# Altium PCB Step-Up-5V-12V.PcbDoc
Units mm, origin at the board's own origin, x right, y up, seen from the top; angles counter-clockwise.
Board outline 43.5 x 30 mm, 2 copper layers (Top Layer, Bottom Layer), stack 1.601 mm thick; 18 components, 9 nets, 46 pads, 0 vias.
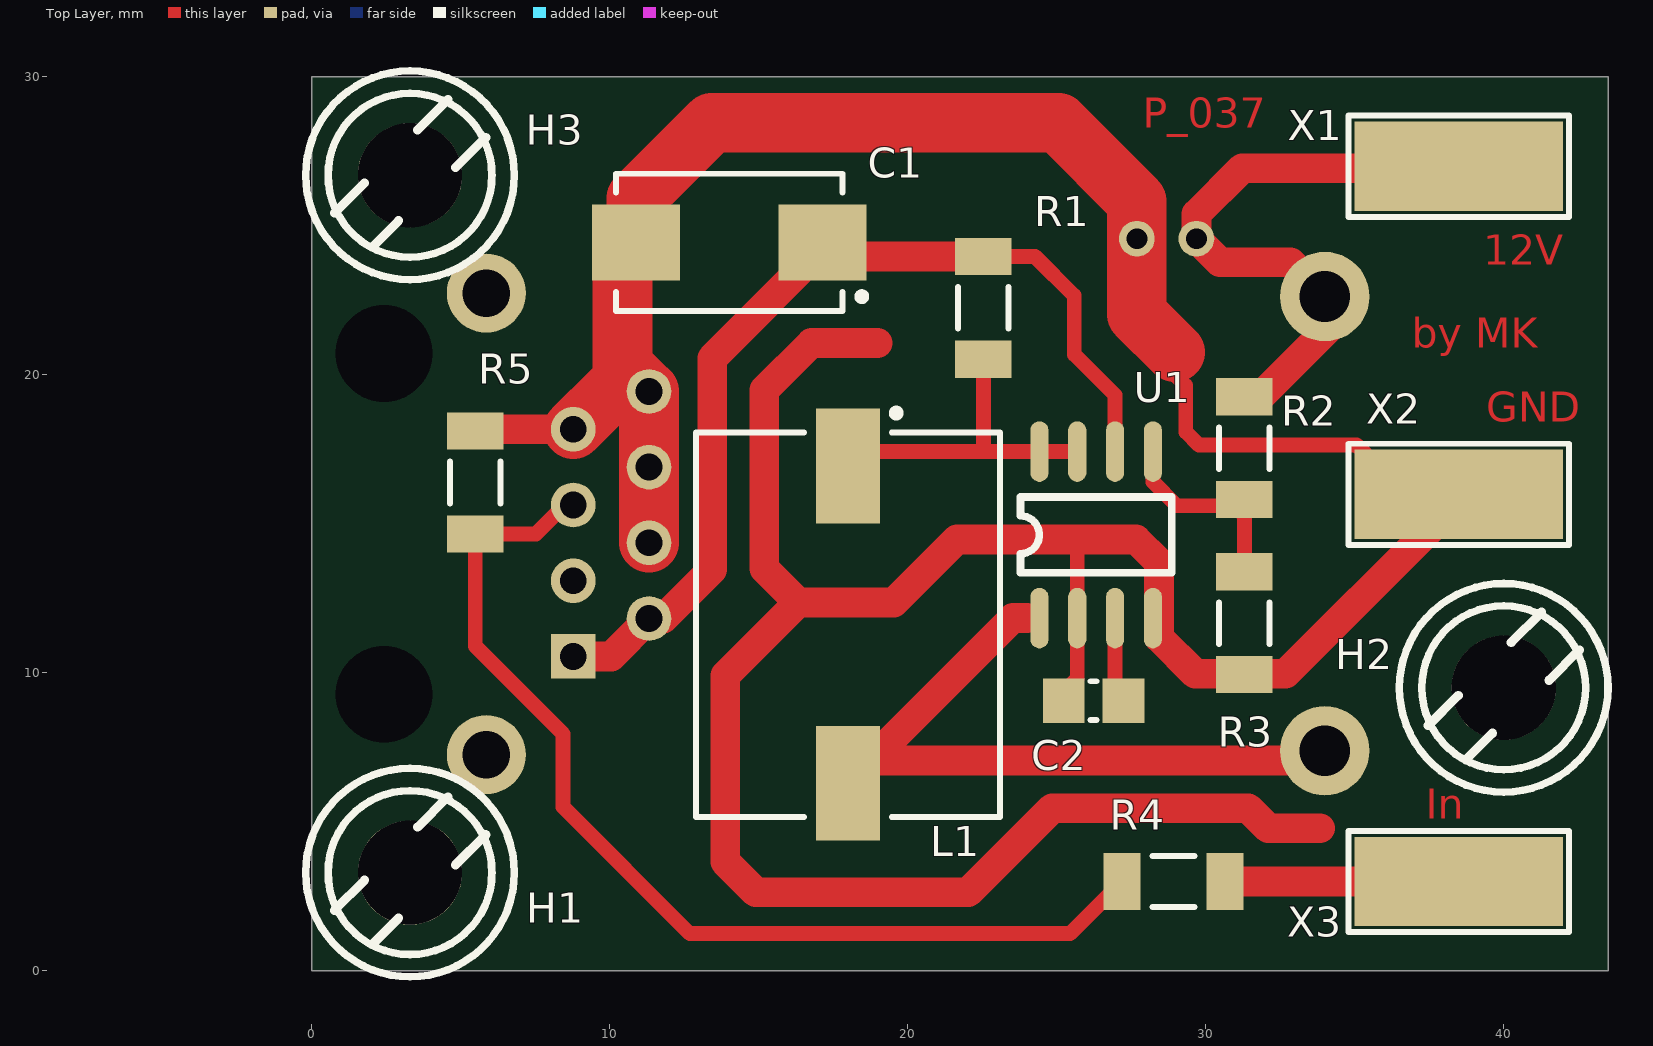
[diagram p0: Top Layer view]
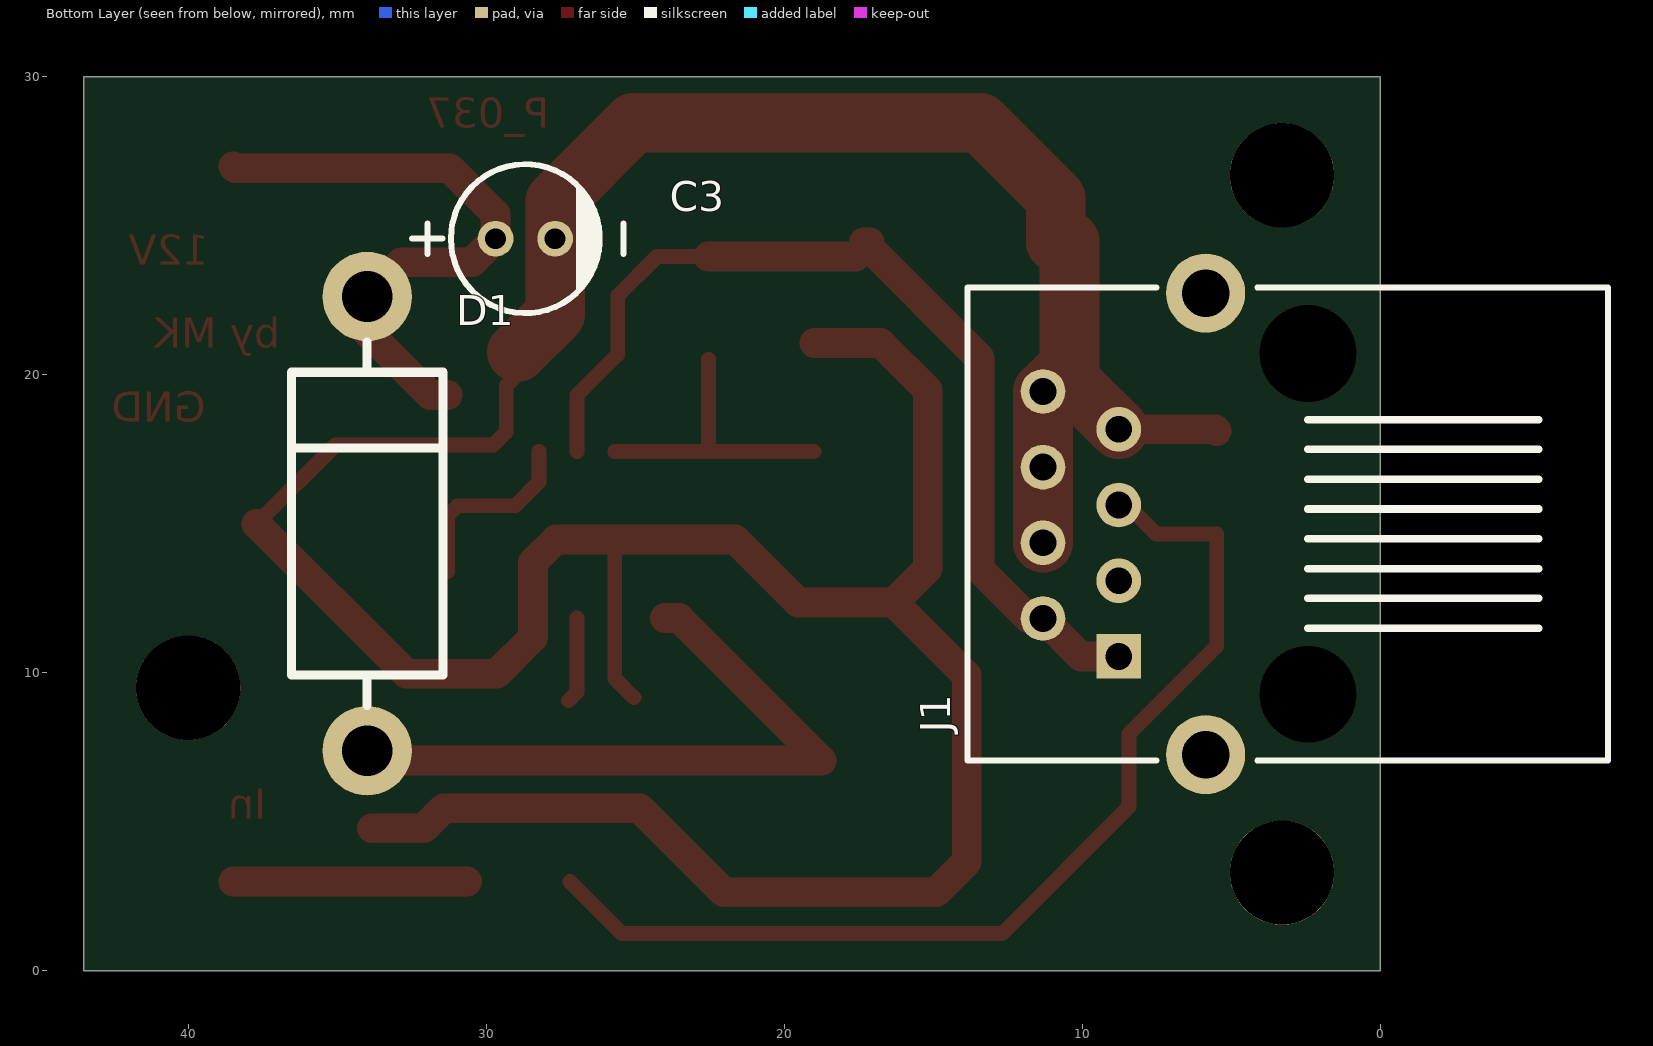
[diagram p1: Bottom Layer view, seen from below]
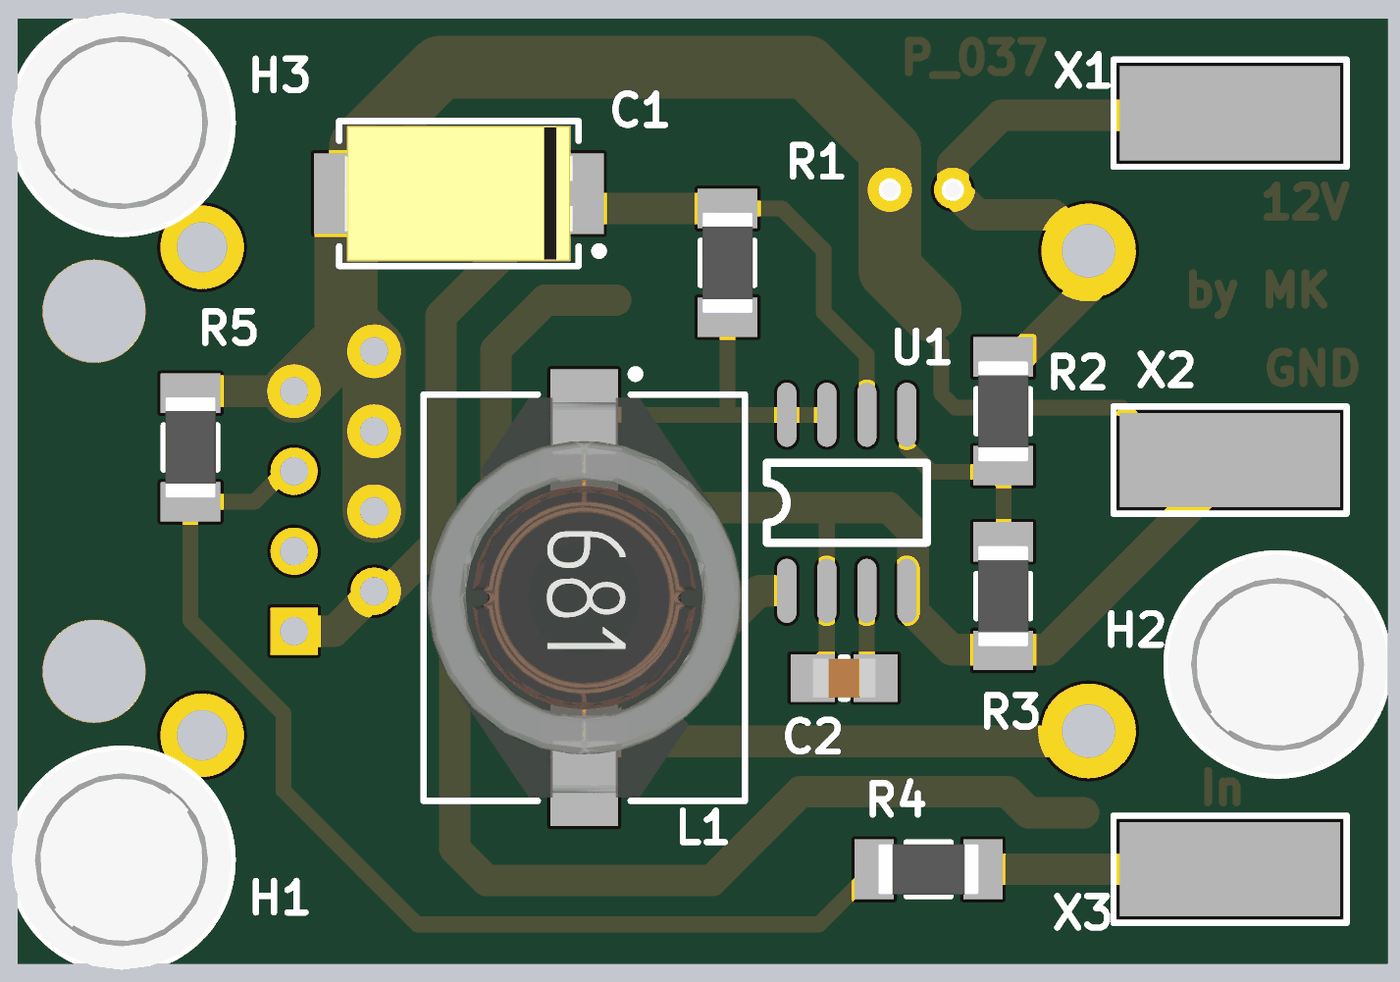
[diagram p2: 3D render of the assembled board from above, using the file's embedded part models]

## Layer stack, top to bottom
Top Layer: signal copper 0.0356
Dielectric: core 1.53, FR-4, Dk 4.8
Bottom Layer: signal copper 0.0356

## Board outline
0,0 0,30 43.5,30 43.5,0

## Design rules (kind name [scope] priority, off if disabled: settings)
Clearance [All] p1: gap=0.2
ComponentClearance [All] p1 off: gap=0.254 collisioncheckmode=3 verticalgap=0.254 showdistances=FALSE
FabricationTestPointUsage TestPointUsage [All] p1: valid=0 allowmultiple=FALSE
FabricationTestpoint Testpoint [All] p1: side=3 testpointundercomponent=TRUE minsize=1.016 maxsize=2.54 preferedsize=1.524 minholesize=0 maxholesize=1.016 preferedholesize=0.813 testpointgrid=0.025 allowsidetop=TRUE allowsidebottom=TRUE usegrid=TRUE gridtolerance=0
HoleSize [All] p1: absolutevalues=TRUE maxlimit=4 minlimit=0.025 maxpercent=80.000 minpercent=20.000
PlaneConnect [All] p1: planeconnectstyle=Relief reliefexpansion=0.5 reliefentries=4 reliefconductorwidth=0.2 reliefairgap=0.2
PolygonConnect [All] p1: connectstyle=Direct reliefconductorwidth=1 reliefentries=4 polygonreliefangle="90 Angle" airgapwidth=0.254
RoutingVias [All] p1: holewidth=0.5 width=0.9 viastyle="Through Hole" minholewidth=0.4 minwidth=0.8 maxholewidth=0.711 maxwidth=1.27
SilkscreenOverComponentPads [All] p1: minsilkscreentomaskgap=0.254
SolderMaskExpansion [All] p1: expansion=0.102
Width [All] p1: maxlimit=10 minlimit=0.2 preferedwidth=0.5
22 further rules are at their usual default settings.

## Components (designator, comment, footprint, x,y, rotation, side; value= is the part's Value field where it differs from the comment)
C1 "100uF" CAPMP7343X31M 14.01,24.45 r180 top
C2 "1,5nF" CAPC2012X09M 26.24,9.07 r180 top
C3 "330uF" ELK_RM020_5x11 28.69,24.57 r180 bottom
D1 "1N5819" DO-201 34,7.39 r90 bottom
H1 "Hole 3,5mm" M3+SCHEIBE 3.3,3.3 r0 top
H2 "Hole 3,5mm" M3+SCHEIBE 40,9.5 r0 top
H3 "Hole 3,5mm" M3+SCHEIBE 3.3,26.7 r0 top
J1 "MEBP 8-8G" "RJ45-JACK-MEBP 8-8G" 8.78,10.555 r90 bottom (schematic designator J4)
L1 "100uH" INDM127100X52M 17.99,11.62 r270 top
R1 "0R33" RESC3216X06M 22.54,22.25 r90 top
R2 "10k" RESC3216X06M 31.29,17.54 r270 top
R3 "1k" RESC3216X06M 31.29,11.67 r270 top
R4 "1k" RESC3216X06M 28.92,3 r180 top
R5 "330R" RESC3216X06M 5.49,16.39 r270 top
U1 "MC34063A" SO-8 24.42,11.84 r90 top
X1 "Ground" GND_PAD3 38.49,27 r180 top
X2 "Ground" GND_PAD3 38.49,15.99 r0 top
X3 "Ground" GND_PAD3 38.49,3 r0 top

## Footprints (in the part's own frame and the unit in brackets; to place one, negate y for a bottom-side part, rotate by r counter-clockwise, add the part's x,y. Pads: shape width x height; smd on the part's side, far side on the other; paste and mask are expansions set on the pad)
CAPC2012X09M [mm] "Chip Capacitor, 2-Leads, Body 2,0x1,3mm, IPC Low Density"
  rect 1.4x1.5 smd: 1(-1,0) 2(1,0)
  silkscreen extent -0.1,-0.65 0.1,0.65, body extent -1,-0.63 1,0.62, height 0.79
CAPMP7343X31M [mm] "Molded Capacitor, 2-Leads, Body 7,3x4,3mm, IPC Low Density"
  rect 2.95x2.55 smd: 1(-3.125,0) 2(3.125,0)
  silkscreen extent -4.58,-2.3 3.8,2.3, body extent -3.65,-2.15 3.65,2.15, height 2.8
DO-201 [mm]
  round 3 hole 1.7: A(0,0) K(15.24,0)
  silkscreen extent 1.52,-2.54 13.72,2.54
ELK_RM020_5x11 [mm]
  round 1.2 hole 0.7: 1(-1,0) 2(1,0)
  silkscreen extent -3.8,-2.5 3.29,2.5, body extent -2.5,-2.5 2.49,2.5, height 11.01
GND_PAD3 [mm]
  rect 7x3 smd: 1(0,0)
  silkscreen extent -3.7,-1.7 3.7,1.7
INDM127100X52M [mm] "Molded Inductor, 2-Leads, Body 12,7x10,0mm, IPC Low Density"
  rect 3.85x2.15 smd: 1(-5.325,0) 2(5.325,0)
  silkscreen extent -7.22,-5.1 6.45,5.1, body extent -6.35,-5 6.35,5, height 4.89
M3+SCHEIBE [mm] "Bohrung M3 + Schraube/Scheibe"
  round 3.5 hole 3.5 unplated: 1(0,0)
  silkscreen extent -3.5,-3.5 3.5,3.5, body extent -3.5,-3.5 3.5,3.5, height 2.5
RESC3216X06M [mm] "Chip Resistor, 2-Leads, Body 3,3x1,6mm, IPC Low Density"
  rect 1.25x1.9 smd: 1(-1.725,0) 2(1.725,0)
  silkscreen extent -0.7,-0.85 0.7,0.85, body extent -1.6,-0.8 1.6,0.8, height 0.59
"RJ45-JACK-MEBP 8-8G" [mm] "Connector; PCB Jack, Thru-Hole; 1-Port, 8 Positions, 8 Loaded; Shielded without Lightpipes; Left Angle"
  rect 1.5x1.5 hole 0.9: 1(0,0)
  round 1.5 hole 0.9: 2(1.27,2.54) 3(2.54,0) 4(3.81,2.54) 5(5.08,0) 6(6.35,2.54) 7(7.62,0) 8(8.89,2.54)
  round 2.65 hole 1.6: MH1(-3.3,-2.921) MH2(12.19,-2.921)
  round 2.95 hole 3.25: MH3(-1.27,-6.35) MH4(10.16,-6.35)
  silkscreen extent -3.49,-16.42 12.38,5.08
SO-8 [mil]
  oval 80x24 smd: 1(0,0) 2(0,-50) 3(0,-100) 4(0,-150) 5(220,-150) 6(220,-100) 7(220,-50) 8(220,0)
  silkscreen extent 60,-175 160,25

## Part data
C1: library part 33UF_6032, "Capacitor Tantalum Case D"
C2: library part 1,5NF_0805, "Capacitor X7R SMD"
C3: library part 100UF_RM2.0_16V, "Capacitor Aluminum Electrolytic 16V 100uF"
D1: library part 1N5822_DO-201, "Schottkydiode 3A/40V"
H1 H2 H3: library part HOLE_3_5, "Bohrung 3.5mm"
J1: library part "RJ45-JACK-MEBP 8-8G", "Right Angle, Standard Profile, External Shield PCB Jack"
L1: library part WE-PD-3-L_10uH, "SMD Shielded Power Inductor WE-PD3, L=10.0 µH"
R1: library part 0R33_1206, "SMD Resistor"
R2: library part 10K_1206, "SMD Resistor"
R3 R4: library part 1K_1206, "SMD Resistor"
R5: library part 330R_1206, "SMD Resistor"
X1 X2 X3: library part GND_PAD3, "Groundpad"

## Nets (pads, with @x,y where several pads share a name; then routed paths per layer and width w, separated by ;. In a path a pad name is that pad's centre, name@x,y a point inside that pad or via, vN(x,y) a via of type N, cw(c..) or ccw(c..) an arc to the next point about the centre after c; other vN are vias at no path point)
GND: C1.2 C2.2 C3.2 J1.4 J1.6 J1.7 J1.8 R3.2 R5.1 U1.2 U1.4 X2.1 | length 132
  Top Layer w0.5: C2.2@25.05,9.17 25.69,9.81 U1.2 25.69,14.48 ; 28.59,20.38 29.33,19.64 29.33,18.09 29.77,17.65 35.06,17.65 X2.1@37.71,15
  Top Layer w1: R5.1 5.55,18.175 J1.7 ; 18.99,21.07 16.77,21.07 15.19,19.49 15.19,13.5 16.33,12.36 ; 33.84,4.79 32.1,4.79 31.43,5.46 24.85,5.46 22.03,2.64 14.9,2.64 13.88,3.66 13.88,9.91 16.33,12.36 ; X2.1@37.71,15 32.68,9.97 29.65,9.97 28.43,11.19 28.43,13.71 27.66,14.48 25.69,14.48 21.65,14.48 19.53,12.36 16.33,12.36
  Top Layer w2: J1.7 10.05,19.445 J1.8 ; C1.2@10.43,24.49 10.43,20.335 J1.8 ; C1.2 10.885,25.925 13.42,28.46 25.06,28.46 27.69,25.83 C3.2 27.69,22.04 28.97,20.76 ; J1.4 J1.6 J1.8
MESS-OUT: J1.5 R4.2 R5.2 | length 35.3
  Top Layer w0.5: J1.5 8.495,15.635 7.525,14.665 R5.2 5.49,10.9 8.44,7.95 8.44,5.5 12.69,1.25 25.445,1.25 R4.2
NetC2_1: C2.1 U1.3 | length 2.9
  Top Layer w0.5: U1.3 26.96,9.35 C2.1
NetD1_A: D1.A L1.2 U1.1 | length 22.6
  Top Layer w1: 24,11.84 23.535,11.84 18.755,7.06 33.67,7.06 D1.A
NetL1_1: L1.1 R1.1 U1.7 U1.8 | length 9.8
  Top Layer w0.5: L1.1@19.002,17.428 22.54,17.428 ; R1.1 22.54,17.428 ; U1.7 U1.8 22.54,17.428
NetR2_2: R2.2 R3.1 U1.5 | length 6.4
  Top Layer w0.5: U1.5 28.23,16.41 29.03,15.61 30.96,15.61 31.3,15.27 R3.1@31.3,13.4
NetR4_1: R4.1 X3.1 | length 7.8
  Top Layer w1: R4.1 X3.1
VCC_IN: C1.1 J1.1 J1.2 R1.2 U1.6 | length 33.6
  Top Layer w0.5: R1.2 24.275,23.975 25.59,22.66 25.59,20.69 26.96,19.32 U1.6
  Top Layer w1: J1.1 10.05,10.555 J1.2 11.795,11.825 13.44,13.47 13.44,20.56 17.33,24.45 C1.1 17.233,24.353 17.61,23.975 R1.2
VCC_OUT: C3.1 D1.K R2.1 X1.1 | length 19.1
  Top Layer w1: R2.1@31.3,19.33 31.88,19.33 D1.K@34.1,21.55 ; D1.K 32.85,23.78 30.48,23.78 C3.1 29.69,25.4 31.223,26.933 38.423,26.933 X1.1
pads on no net: H1.1 H2.1 H3.1 J1.3 J1.MH1 J1.MH2 J1.MH3 J1.MH4

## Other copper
Top Layer:
  text "P_037" at 27.89,28.29 h1
  text "12V" at 39.32,23.7 h1
  text "by MK" at 36.91,20.91 h1
  text "GND" at 39.42,18.42 h1
  text "In" at 37.39,5.11 h1
  text "2" at 119.708,-88.54 h1.27
  text "Top Layer" at 132.288,-88.64 h1.27
Bottom Layer:
  text "3" at 119.708,-88.54 h1.27
  text "Bottom Layer" at 132.288,-88.64 h1.27

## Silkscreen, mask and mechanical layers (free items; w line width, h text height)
Top Overlay:
  text "1" at 119.878,-88.53 h1.27
  text "Top Overlay" at 132.288,-88.64 h1.27
Bottom Overlay:
  text "4" at 119.708,-88.54 h1.27
  text "Bottom Overlay" at 132.288,-88.64 h1.27
Mechanical 1:
  the board outline again, w0.4
Mechanical 16:
  lines w0.127: -125.29,-46.26 -120.21,-46.26 ; -125.29,2 -120.21,2 ; -125.29,50.26 -120.21,50.26 ; -55.29,-94.52 -55.29,-89.44 ; -55.29,93.44 -55.29,98.52 ; 14.71,-94.52 14.71,-89.44 ; 14.71,93.44 14.71,98.52 ; 84.71,-94.52 84.71,-89.44 ; 84.71,93.44 84.71,98.52 ; 149.63,-46.26 154.71,-46.26 ; 149.63,2 154.71,2 ; 149.63,50.26 154.71,50.26 ; -125.29,-94.52 -125.29,98.52 154.71,98.52 154.71,-94.52 -125.29,-94.52 ; -120.21,-89.44 149.63,-89.44 149.63,93.44 -120.21,93.44 -120.21,-89.44
  lines w0.2: -13.203,-89.241 -13.203,-69.429 54.551,-69.452 ; 54.569,-89.44 54.569,-69.44 149.569,-69.44 ; 54.569,-86.44 131.569,-86.44 149.569,-86.44 ; 54.569,-83.44 111.569,-83.44 ; 54.569,-78.44 111.569,-78.44 ; 64.569,-83.44 64.569,-78.44 ; 96.525,-86.44 96.525,-78.44 ; 111.569,-89.44 111.569,-69.44 ; 131.569,-89.44 131.569,-69.44
  text "1" at -89.044,95.091 h1.78
  text "2" at -16.4,95.091 h1.78
  text "3" at 56.752,95.091 h1.78
  text "4" at 129.65,95.091 h1.78
  text "A" at -123.385,72.079 h1.78
  text "A" at 151.535,72.079 h1.78
  text "B" at -123.385,24.022 h1.78
  text "B" at 151.535,24.022 h1.78
  text "C" at -123.385,-24.492 h1.78
  text "C" at 151.535,-24.492 h1.78
  text "D" at -123.385,-72.498 h1.78
  text "D" at 151.535,-72.498 h1.78
  text "Copying of this document, and giving it to others and the use or comunication of the" at -12.009,-72.756 h1
  text "Step-Up-5V-12V" at 57.158,-74.62 h2.27
  text "contents therof, ar forbidden without express authority. Offenders are liable to the" at -12.009,-74.788 h1
  text "payment of damages. All rights are reserved in the event of the grant of a patent or" at -12.009,-76.82 h1
  text "the registration of a utility model or design." at -12.009,-78.852 h1
  text "by MK" at 133.71,-79.73 h3
  text "Weitergabe sowie vervielfaeltigung dieser Unterlage, Verwertung und Mitteilung ihres Inhalts" at -12.009,-81.392 h1
  text "Size:" at 55.269,-81.64 h1.27
  text "A4" at 60.569,-81.64 h1.27
  text "Number:" at 65.369,-81.64 h1.27
  text "Revision: 1.0" at 97.659,-81.64 h1.27
  text "1.0" at 76.47,-81.79 h1.27
  text "nicht gestattet, soweit nicht ausdruecklich zugestanden. Zuwiederhandlung verpflichtet zu" at -12.009,-83.424 h1
  text "Schadensersatz. Alle Rechte fuer den Fall der Patenterteilung oder Gebrauchsmuster-" at -12.009,-85.456 h1
  text ".Pcb_File_Name_No_Path" at 55.269,-85.54 h1.27
  text "Project: P_025" at 97.659,-85.704 h1.27
  text "Eintragungen vorbehalten." at -12.009,-87.488 h1
  text "Print Date:" at 80.17,-88.47 h1.27
  text "Date:" at 55.269,-88.54 h1.27
  text "29.04.2012" at 61.069,-88.54 h1.27
  text ".Print_Date" at 91.789,-88.54 h1.27
  text "Sheet    of 4" at 113.069,-88.54 h1.27
  text "1" at -89.044,-92.869 h1.78
  text "2" at -16.4,-92.869 h1.78
  text "3" at 56.752,-92.869 h1.78
  text "4" at 129.65,-92.869 h1.78

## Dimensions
0,0 to 0,30 on Mechanical 14
0,0 to 43.5,0 on Mechanical 14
